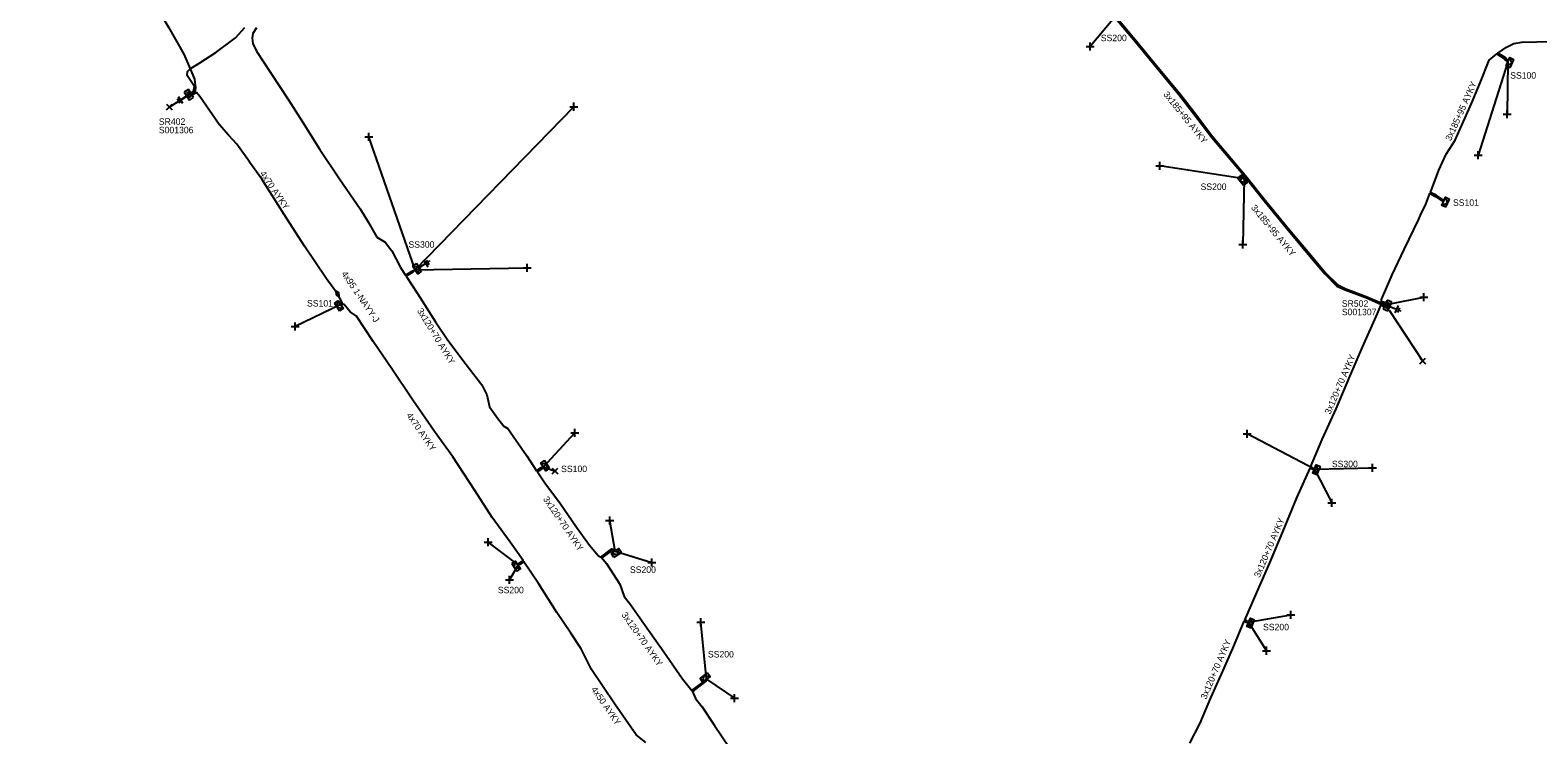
# Model space of a CAD drawing. Extents: x -763093 to -760976, y -1155572 to -1152009.
# Drawn here: x -762677.1 to -762444.1, y -1154946.3 to -1154837.4 of the extents above; entities that cross this region are included whole.
import ezdxf

# ---------------------------------------------------------------- set-up
doc = ezdxf.new("R2010")
doc.units = 0
for name, color, linetype in [('Vrstva 1', 7, 'Continuous'), ('Vrstva 14', 7, 'Continuous'), ('Vrstva 15', 7, 'Continuous'), ('Vrstva 19', 7, 'Continuous'), ('Vrstva 28', 7, 'Continuous'), ('Vrstva 29', 7, 'Continuous'), ('Vrstva 30', 7, 'Continuous'), ('Vrstva 31', 7, 'Continuous'), ('Vrstva 33', 7, 'Continuous'), ('Vrstva 34', 7, 'Continuous'), ('Vrstva 4', 7, 'Continuous'), ('Vrstva 5', 7, 'Continuous'), ('Vrstva 59', 7, 'Continuous'), ('Vrstva 6', 7, 'Continuous'), ('Vrstva 8', 7, 'Continuous'), ('Vrstva 9', 7, 'Continuous')]:
    doc.layers.add(name, color=color, linetype=linetype)

# ---------------------------------------------------------------- blocks, each defined once
blk = doc.blocks.new('NN870')
at = {"layer": 'Vrstva 4'}
for points in [[(0, -0.25), (0.5, 0), (0, 0.25), (-0.5, 0), (0, -0.25)], [(0.37, 0), (0, 0.19), (-0.36, 0), (0, -0.19), (0.37, 0)], [(0.24, 0), (0, 0.12), (-0.25, 0), (0, -0.12), (0.24, 0)], [(0.12, 0), (0, 0.06), (-0.13, 0), (0, -0.06), (0.12, 0)]]:
    blk.add_lwpolyline(points, dxfattribs=at)
blk = doc.blocks.new('NN800')
at = {"layer": 'Vrstva 1'}
for points in [[(-0.44, 0.44), (0.44, -0.44)], [(-0.44, -0.44), (0.44, 0.44)]]:
    blk.add_lwpolyline(points, dxfattribs=at)
blk = doc.blocks.new('NN620')
at = {"layer": 'Vrstva 8'}
for points in [[(0.75, 0), (-0.75, 0)], [(-0.75, 0), (-0.75, -0.75)], [(0.75, -0.75), (0.75, 0)], [(-0.75, -0.75), (0.75, -0.75)], [(0.37, -0.18), (-0.38, -0.18)], [(-0.38, -0.18), (-0.38, -0.56)], [(-0.38, -0.56), (0.37, -0.56)], [(0.32, -0.23), (-0.33, -0.23)], [(-0.33, -0.23), (-0.33, -0.51)], [(-0.33, -0.51), (0.32, -0.51)], [(0.27, -0.27), (-0.28, -0.27)], [(-0.28, -0.27), (-0.28, -0.46)], [(-0.28, -0.46), (0.27, -0.46)], [(0.23, -0.32), (-0.23, -0.32)], [(-0.23, -0.32), (-0.23, -0.42)], [(-0.23, -0.42), (0.23, -0.42)], [(-0.19, -0.37), (0.19, -0.37)], [(0.23, -0.42), (0.23, -0.32)], [(0.27, -0.46), (0.27, -0.27)], [(0.32, -0.51), (0.32, -0.23)], [(0.37, -0.56), (0.37, -0.18)]]:
    blk.add_lwpolyline(points, dxfattribs=at)
blk = doc.blocks.new('NN630')
at = {"layer": 'Vrstva 9'}
for points in [[(0, -0.7), (-0.7, 0)], [(-0.7, -0.7), (-0.7, 0), (0.7, 0), (0.7, -0.7)], [(-0.7, -0.7), (0.7, -0.7)], [(0, -0.7), (0.7, 0)]]:
    blk.add_lwpolyline(points, dxfattribs=at)
blk = doc.blocks.new('NN810')
at = {"layer": 'Vrstva 14'}
for points in [[(0.63, -1.89), (-0.62, -1.89)], [(0.39, -2.2), (-0.4, -2.2)], [(0, -0.64), (0, -1.89)], [(0, -2.52), (-0.12, -2.52)], [(0.14, -2.52), (0, -2.52)]]:
    blk.add_lwpolyline(points, dxfattribs=at)

msp = doc.modelspace()

# ---------------------------------------------------------------- linework, layer by layer
at = {"layer": 'Vrstva 5'}
for points in [[(-762677.14, -1154801.92), (-762675.76, -1154804.21), (-762673.22, -1154808.16), (-762670.17, -1154813), (-762667.94, -1154816.82), (-762665.53, -1154820.95), (-762664.04, -1154823.63), (-762664.91, -1154824.18), (-762665.11, -1154824.43), (-762664.8, -1154824.35), (-762663.94, -1154823.81), (-762662.65, -1154825.93), (-762660.82, -1154828.7), (-762658.79, -1154831.85), (-762655.78, -1154836.95), (-762653.37, -1154841.13), (-762652.4, -1154843.39), (-762651.72, -1154844.97), (-762651.56, -1154846.3), (-762651.71, -1154846.97), (-762652.16, -1154847.24)], [(-762509.38, -1154835.54), (-762506.33, -1154839.21), (-762503.03, -1154843.22), (-762499.6, -1154847.33), (-762497.33, -1154850.26), (-762494.49, -1154854), (-762491.67, -1154857.34), (-762489.31, -1154860.13), (-762489.5, -1154860.37), (-762489.18, -1154860.28), (-762486.42, -1154863.76), (-762482.91, -1154868.04), (-762479.34, -1154872.33), (-762477.06, -1154875.05), (-762475.17, -1154876.93), (-762473.9, -1154877.52), (-762470.72, -1154878.72), (-762468.31, -1154879.77), (-762467.84, -1154879.85)], [(-762509.29, -1154835.34), (-762506.17, -1154839.09), (-762502.87, -1154843.1), (-762499.44, -1154847.21), (-762497.17, -1154850.14), (-762494.33, -1154853.88), (-762491.51, -1154857.22), (-762489.08, -1154860.09), (-762486.26, -1154863.64), (-762482.75, -1154867.92), (-762479.18, -1154872.21), (-762476.92, -1154874.91), (-762475.05, -1154876.77), (-762473.82, -1154877.34), (-762470.64, -1154878.54), (-762468.25, -1154879.57), (-762467.77, -1154879.67)], [(-762652.27, -1154847.07), (-762651.89, -1154846.85), (-762651.72, -1154846.09), (-762652.86, -1154844.39), (-762652.83, -1154843.81), (-762652.4, -1154843.39), (-762650.91, -1154842.45), (-762648.46, -1154840.87), (-762645.4, -1154838.58), (-762643.97, -1154836.98)], [(-762642.17, -1154837.04), (-762642.72, -1154837.89), (-762642.85, -1154838.66), (-762642.7, -1154839.44), (-762642.14, -1154840.65), (-762639.97, -1154843.96), (-762637.22, -1154848.18), (-762635.04, -1154851.57), (-762632.37, -1154855.86), (-762629.32, -1154860.35), (-762626.13, -1154865), (-762624.85, -1154867.1), (-762623.56, -1154869.38), (-762622.29, -1154870.18), (-762621.25, -1154871.49), (-762619.91, -1154874.05), (-762619.12, -1154875.25), (-762618.1, -1154874.65), (-762617.61, -1154874.44), (-762618, -1154874.81), (-762619.01, -1154875.41), (-762617.25, -1154878.1), (-762614.47, -1154882.46), (-762612.56, -1154885.28), (-762609.74, -1154889.03), (-762607.35, -1154892.18), (-762606.54, -1154893.73), (-762606.14, -1154895.59), (-762604.88, -1154897.4), (-762603.93, -1154898.56), (-762603.32, -1154898.94), (-762600.38, -1154903.17), (-762598.86, -1154905.48), (-762598.14, -1154904.98), (-762597.82, -1154904.88), (-762598.04, -1154905.16), (-762598.74, -1154905.64), (-762597.5, -1154907.48), (-762595.28, -1154910.44), (-762592.69, -1154914.2), (-762590.71, -1154916.95), (-762589.32, -1154918.62), (-762588.96, -1154918.81), (-762587.25, -1154917.55), (-762586.93, -1154917.67), (-762586.72, -1154917.87), (-762586.99, -1154917.87), (-762587.23, -1154917.77), (-762588.78, -1154918.9), (-762588.05, -1154919.78), (-762586.02, -1154923.01), (-762585.32, -1154924.91), (-762584.36, -1154926.12), (-762582.18, -1154929.22), (-762579.22, -1154933.44), (-762576.31, -1154937.62), (-762574.87, -1154939.43), (-762573.3, -1154938.23), (-762572.63, -1154937.67), (-762572.69, -1154937.99), (-762574.77, -1154939.6), (-762574.32, -1154940.65), (-762573.3, -1154941.93), (-762571.36, -1154944.85), (-762569.09, -1154948.16)], [(-762467.64, -1154879.49), (-762468.28, -1154879.36), (-762468.28, -1154879.03), (-762466.65, -1154875.2), (-762464.78, -1154871.27), (-762462.5, -1154866.61), (-762462.25, -1154865.96), (-762461.42, -1154864.26), (-762460.82, -1154862.66), (-762459.93, -1154863.09), (-762458.98, -1154863.76), (-762458.69, -1154863.84), (-762458.87, -1154863.58), (-762459.83, -1154862.91), (-762460.74, -1154862.48), (-762459.42, -1154859.03), (-762458.29, -1154856.56), (-762456.92, -1154854.41), (-762454.38, -1154848.74), (-762453.05, -1154845.52), (-762451.64, -1154842.06), (-762450.48, -1154841.07), (-762449.32, -1154841.79), (-762449.07, -1154842.07), (-762448.74, -1154842.28), (-762448.93, -1154841.92), (-762449.2, -1154841.63), (-762450.31, -1154840.94), (-762448.96, -1154840.05), (-762447.83, -1154839.44), (-762446.62, -1154839.27), (-762442, -1154839.15)], [(-762629.63, -1154878.14), (-762631.33, -1154875.81), (-762634.73, -1154870.76), (-762637.89, -1154865.88), (-762641.35, -1154860.41), (-762643.23, -1154857.77), (-762643.24, -1154857.72), (-762645.21, -1154855), (-762646.44, -1154853.69), (-762647.92, -1154852), (-762650.89, -1154847.64), (-762651.43, -1154847.02), (-762652.06, -1154847.39)], [(-762629.13, -1154879.8), (-762628.84, -1154879.57), (-762629.63, -1154878.14)], [(-762601.74, -1154920.01), (-762601.57, -1154919.76), (-762600.95, -1154919.36), (-762602.94, -1154916.51), (-762605.73, -1154912.68), (-762608.42, -1154908.53), (-762611.83, -1154903.31), (-762614.65, -1154899.43), (-762617.97, -1154894.54), (-762621.24, -1154889.75), (-762624.12, -1154885.48), (-762626.71, -1154881.58), (-762627.69, -1154880.94), (-762628.63, -1154879.77), (-762629.13, -1154879.8)], [(-762497.91, -1154947.58), (-762496.31, -1154944.47), (-762494.64, -1154940.57), (-762493.04, -1154936.89), (-762491.28, -1154932.91), (-762489.51, -1154928.72), (-762489.18, -1154928.84), (-762488.82, -1154928.87), (-762489.11, -1154928.66), (-762489.43, -1154928.54), (-762487.55, -1154924.28), (-762485.56, -1154919.69), (-762483.56, -1154914.92), (-762481.36, -1154909.64), (-762479.32, -1154905.08), (-762479, -1154905.19), (-762478.65, -1154905.21), (-762478.93, -1154905.01), (-762479.24, -1154904.9), (-762477.44, -1154900.65), (-762475.28, -1154895.91), (-762473.19, -1154890.9), (-762471.22, -1154886.36), (-762468.93, -1154881.16), (-762468.4, -1154879.95), (-762467.92, -1154880.04)], [(-762581.98, -1154947.47), (-762583.46, -1154946.26), (-762586.77, -1154941.52), (-762590.36, -1154936.2), (-762591.98, -1154933.01), (-762593.58, -1154930.54), (-762595.75, -1154927.35), (-762598.59, -1154922.89), (-762600.83, -1154919.52), (-762601.45, -1154919.95), (-762601.74, -1154920.01)]]:
    msp.add_lwpolyline(points, dxfattribs=at)
at = {"layer": 'Vrstva 59'}
for points in [[(-762509.83, -1154835.73), (-762513.31, -1154839.9)], [(-762448.74, -1154842.28), (-762453.33, -1154856.71)], [(-762448.74, -1154842.28), (-762448.88, -1154850.38)], [(-762652.98, -1154847.61), (-762655.62, -1154849.29)], [(-762617.61, -1154874.44), (-762593.13, -1154849.22)], [(-762617.61, -1154874.44), (-762624.81, -1154853.88)], [(-762489.5, -1154860.37), (-762502.56, -1154858.38)], [(-762489.5, -1154860.37), (-762489.74, -1154870.49)], [(-762617.61, -1154874.44), (-762600.31, -1154874.13)], [(-762629.13, -1154879.8), (-762636.17, -1154883.2)], [(-762466.69, -1154879.63), (-762461.74, -1154878.64)], [(-762467.12, -1154880.64), (-762461.94, -1154888.5)], [(-762597.82, -1154904.88), (-762592.94, -1154899.63)], [(-762478.65, -1154905.21), (-762489.06, -1154899.75)], [(-762597.82, -1154904.88), (-762596.01, -1154905.51)], [(-762478.65, -1154905.21), (-762469.69, -1154905)], [(-762478.65, -1154905.21), (-762475.97, -1154910.43)], [(-762586.72, -1154917.87), (-762587.57, -1154913.16)], [(-762601.74, -1154920.01), (-762606.33, -1154916.5)], [(-762586.72, -1154917.87), (-762581.06, -1154919.63)], [(-762601.74, -1154920.01), (-762603.04, -1154922.33)], [(-762572.63, -1154937.67), (-762573.5, -1154928.88)], [(-762488.82, -1154928.87), (-762482.31, -1154927.75)], [(-762488.82, -1154928.87), (-762486.06, -1154933.27)], [(-762572.63, -1154937.67), (-762568.26, -1154940.6)]]:
    msp.add_lwpolyline(points, dxfattribs=at)

# ---------------------------------------------------------------- block references
at = {"layer": 'Vrstva 15'}
for p, rotation in [((-762652.28, -1154847.19), -57.55336665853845), ((-762617.61, -1154874.44), 122.26000284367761), ((-762467.7, -1154879.78), 66.69798895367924)]:
    msp.add_blockref('NN810', p, dxfattribs=dict(at, rotation=rotation))
at = {"layer": 'Vrstva 19', "rotation": -57.660052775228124}
msp.add_blockref('NN870', (-762629.63, -1154878.14), dxfattribs=at)
at = {"layer": 'Vrstva 28'}
for p, rotation in [((-762652.28, -1154847.19), -57.55336673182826), ((-762467.7, -1154879.78), 65.83873050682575)]:
    msp.add_blockref('NN620', p, dxfattribs=dict(at, rotation=rotation))
at = {"layer": 'Vrstva 31'}
for p, rotation in [((-762448.74, -1154842.28), 65.36848605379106), ((-762489.5, -1154860.37), -52.07269740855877), ((-762458.69, -1154863.84), 64.83486202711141), ((-762617.61, -1154874.44), 122.87512495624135), ((-762629.13, -1154879.8), -56.84618885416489), ((-762597.82, -1154904.88), 123.95793326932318), ((-762478.65, -1154905.21), 67.22410001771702), ((-762601.74, -1154920.01), -55.85844445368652), ((-762586.72, -1154917.87), 33.00782775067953), ((-762488.82, -1154928.87), 67.00772774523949), ((-762572.63, -1154937.67), -145.18444998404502)]:
    msp.add_blockref('NN630', p, dxfattribs=dict(at, rotation=rotation))
at = {"layer": 'Vrstva 34'}
for p, rotation in [((-762513.31, -1154839.91), 45), ((-762593.13, -1154849.22), 45), ((-762448.88, -1154850.38), 45), ((-762624.81, -1154853.88), 45), ((-762453.33, -1154856.71), 44.99999995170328), ((-762502.56, -1154858.38), 45), ((-762489.74, -1154870.49), 45), ((-762600.31, -1154874.13), 45), ((-762461.74, -1154878.64), 45), ((-762636.17, -1154883.2), 44.99999995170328), ((-762592.94, -1154899.63), 44.99999995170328), ((-762489.06, -1154899.75), 45), ((-762469.69, -1154905), 44.99999995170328), ((-762475.97, -1154910.43), 45), ((-762587.57, -1154913.16), 45), ((-762606.33, -1154916.5), 45.00000009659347), ((-762581.06, -1154919.63), 45), ((-762603.04, -1154922.33), 45), ((-762573.5, -1154928.88), 45), ((-762482.31, -1154927.75), 45), ((-762486.06, -1154933.27), 45), ((-762568.26, -1154940.6), 45)]:
    msp.add_blockref('NN800', p, dxfattribs=dict(at, rotation=rotation))
for p in [(-762655.62, -1154849.29), (-762461.94, -1154888.5), (-762596.01, -1154905.51)]:
    msp.add_blockref('NN800', p, dxfattribs=at)

# ---------------------------------------------------------------- texts
at = {"layer": 'Vrstva 29'}
for s, p in [('S001306', (-762657.25, -1154853.33)), ('S001307', (-762474.42, -1154881.44))]:
    msp.add_text(s, height=1, dxfattribs=at).set_placement(p)
at = {"layer": 'Vrstva 30'}
for s, p in [('SR402', (-762657.25, -1154852.03)), ('SR502', (-762474.42, -1154880.14))]:
    msp.add_text(s, height=1, dxfattribs=at).set_placement(p)
at = {"layer": 'Vrstva 33'}
for s, p in [('SS200', (-762511.67, -1154839.1)), ('SS100', (-762448.4, -1154844.89)), ('SS200', (-762496.25, -1154862.09)), ('SS101', (-762457.24, -1154864.54)), ('SS300', (-762618.67, -1154871.01)), ('SS101', (-762634.35, -1154880.1)), ('SS100', (-762595.08, -1154905.68)), ('SS300', (-762475.96, -1154904.92)), ('SS200', (-762584.44, -1154921.25)), ('SS200', (-762604.86, -1154924.4)), ('SS200', (-762486.6, -1154930.12)), ('SS200', (-762572.39, -1154934.32))]:
    msp.add_text(s, height=1, dxfattribs=at).set_placement(p)
at = {"layer": 'Vrstva 6'}
for s, rotation, p in [('3x185+95 AYKY', 308.797, (-762502.06, -1154847.35)), ('3x185+95 AYKY', 65.881, (-762457.56, -1154854.6)), ('4x70 AYKY', 304.466, (-762641.7, -1154859.57)), ('3x185+95 AYKY', 309.602, (-762488.52, -1154864.86)), ('4x95 1-NAYY-J', 304.103, (-762629.08, -1154875.04)), ('3x120+70 AYKY', 301.483, (-762617.39, -1154880.73)), ('3x120+70 AYKY', 66.698, (-762476.2, -1154896.83)), ('4x70 AYKY', 304.627, (-762619.04, -1154896.92)), ('3x120+70 AYKY', 304.179, (-762597.91, -1154909.85)), ('3x120+70 AYKY', 66.756, (-762487.13, -1154922.08)), ('3x120+70 AYKY', 305.227, (-762585.8, -1154927.74)), ('3x120+70 AYKY', 66.919, (-762495.38, -1154940.87)), ('4x50 AYKY', 304.716, (-762590.49, -1154939.27))]:
    msp.add_text(s, height=1, rotation=rotation, dxfattribs=at).set_placement(p)

doc.saveas('drawing.dxf')
